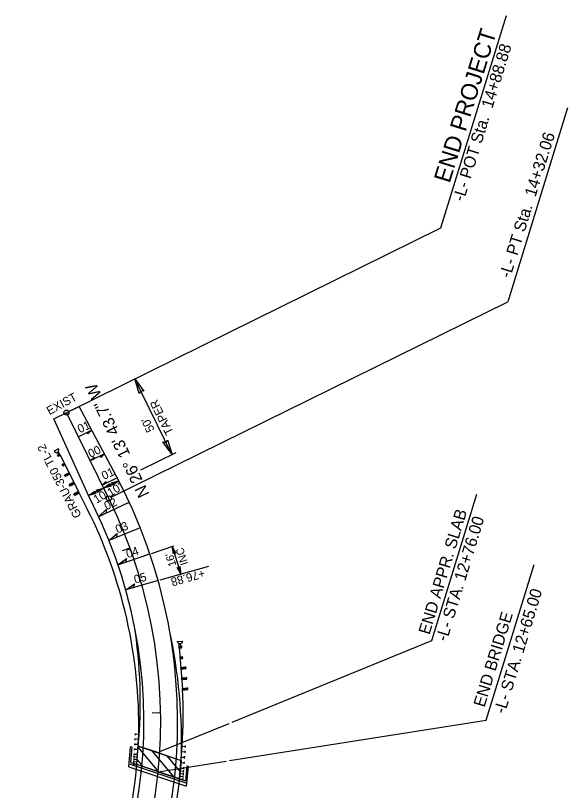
# Model space of a CAD drawing. Extents: x 1348352 to 1349119, y 1028998 to 1029749.
# Drawn here: x 1348790.7 to 1349118.5, y 1029289.4 to 1029749.4 of the extents above; entities that cross this region are included whole.
import ezdxf

# ---------------------------------------------------------------- set-up
doc = ezdxf.new("R2010")
doc.units = 0
for name, color, linetype in [('Default', 7, 'Continuous'), ('Prop Dimension', 7, 'Continuous'), ('Prop Dimension Text', 7, 'Continuous'), ('Prop DSN Text', 7, 'Continuous'), ('Prop EOT', 7, 'Continuous'), ('Prop Guardrail', 7, 'Continuous'), ('Prop Guardrail Anchor Unit CELL', 7, 'Continuous'), ('Prop Horizontal Alignment', 7, 'Continuous'), ('Prop Horizontal Alignment Direction Label', 7, 'Continuous'), ('Prop Horizontal Alignment Station Label', 7, 'Continuous'), ('Prop Horizontal Alignment Tick Small', 7, 'Continuous'), ('Prop Leader Line Medium', 7, 'Continuous'), ('Prop Paved Shoulder', 7, 'Continuous'), ('Prop Roadway Bridge', 7, 'Continuous'), ('Prop Structure Anchor Unit CELL', 7, 'Continuous'), ('Prop Superelevation  Arrow CELL', 7, 'Continuous'), ('Prop Superelevation Label', 7, 'Continuous'), ('Prop Terminator CELL', 7, 'Continuous')]:
    doc.layers.add(name, color=color, linetype=linetype)

msp = doc.modelspace()

# ---------------------------------------------------------------- linework, layer by layer
at = {"layer": 'Default'}
for p, q in [((1348858.09, 1029303.43), (1348858.96, 1029315.21)), ((1348859.96, 1029315.13), (1348858.96, 1029315.21)), ((1348859.27, 1029305.94), (1348859.96, 1029315.13)), ((1348892.5, 1029303.78), (1348891.61, 1029295.07)), ((1348892.3, 1029291.94), (1348893.5, 1029303.68)), ((1348893.5, 1029303.68), (1348892.5, 1029303.78))]:
    msp.add_line(p, q, dxfattribs=at)
for points in [[(1348858.09, 1029303.43), (1348892.3, 1029291.94)], [(1348858.22, 1029305.24), (1348892.48, 1029293.73)], [(1348859.27, 1029305.94), (1348862.2, 1029304.95)], [(1348888.14, 1029296.24), (1348891.61, 1029295.07)]]:
    msp.add_lwpolyline(points, dxfattribs=at)
at = {"layer": 'Prop Dimension'}
for p, q in [((1348883.61, 1029488.84), (1348861.51, 1029533.68)), ((1348836.01, 1029503.29), (1348828.05, 1029499.36)), ((1348843.56, 1029489.17), (1348835.12, 1029485.01)), ((1348865.24, 1029479.79), (1348886.05, 1029490.04)), ((1348834.1, 1029464.45), (1348852.05, 1029473.29)), ((1348851.1, 1029475.05), (1348842.19, 1029470.66)), ((1348840.11, 1029452.07), (1348858.26, 1029460.47)), ((1348864.81, 1029445.29), (1348846.24, 1029437.87)), ((1348871.48, 1029430.11), (1348884.74, 1029434.61)), ((1348883.79, 1029434.29), (1348888.91, 1029417.78)), ((1348851.59, 1029423.36), (1348870.53, 1029429.79)), ((1348905.42, 1029422.42), (1348876.39, 1029414.27)), ((1348875.43, 1029414), (1348856.17, 1029408.59))]:
    msp.add_line(p, q, dxfattribs=at)
at = {"layer": 'Prop EOT'}
for p, q in [((1348813.47, 1029510.02), (1348828.47, 1029517.41)), ((1348852.05, 1029473.29), (1348828.47, 1029517.41)), ((1348834.1, 1029464.45), (1348813.47, 1029510.02)), ((1348855.06, 1029467.16), (1348852.05, 1029473.29)), ((1348837.12, 1029458.33), (1348834.1, 1029464.45))]:
    msp.add_line(p, q, dxfattribs=at)
for radius in [310, 290]:
    msp.add_arc((1348576.98, 1029330.16), radius, 317.4777, 26.2288, dxfattribs=at)
at = {"layer": 'Prop Guardrail'}
msp.add_line((1348828.38, 1029466.35), (1348833.37, 1029456.44), dxfattribs=at)
for centre, radius, start, end in [((1348577.56, 1029327.72), 286.37, 358.983, 26.7112), ((1348591.75, 1029335.59), 298.56, 356.1874, 2.673)]:
    msp.add_arc(centre, radius, start, end, dxfattribs=at)
at = {"layer": 'Prop Guardrail Anchor Unit CELL'}
for p, q in [((1348816.35, 1029492.14), (1348813.73, 1029490.82)), ((1348813.87, 1029490.55), (1348813.73, 1029490.82)), ((1348813.87, 1029490.55), (1348815.16, 1029489.88)), ((1348815.16, 1029489.88), (1348816.25, 1029490.43)), ((1348816.25, 1029490.43), (1348816.49, 1029491.87)), ((1348816.92, 1029489.12), (1348816.25, 1029490.43)), ((1348816.49, 1029491.87), (1348816.35, 1029492.14)), ((1348816.92, 1029489.12), (1348815.57, 1029488.44)), ((1348816.02, 1029487.55), (1348815.57, 1029488.44)), ((1348817.37, 1029488.23), (1348815.57, 1029488.44)), ((1348815.61, 1029490.11), (1348816.27, 1029488.8)), ((1348816.02, 1029487.55), (1348816.92, 1029489.12)), ((1348817.37, 1029488.23), (1348816.02, 1029487.55)), ((1348817.37, 1029488.23), (1348816.92, 1029489.12)), ((1348817.15, 1029488.68), (1348828.38, 1029466.34)), ((1348819.73, 1029483.54), (1348818.38, 1029482.86)), ((1348818.83, 1029481.96), (1348818.38, 1029482.86)), ((1348820.18, 1029482.65), (1348818.38, 1029482.86)), ((1348818.83, 1029481.97), (1348819.73, 1029483.54)), ((1348820.18, 1029482.65), (1348818.83, 1029481.96)), ((1348820.18, 1029482.65), (1348819.73, 1029483.54)), ((1348822.54, 1029477.96), (1348819.83, 1029476.59)), ((1348820.28, 1029475.7), (1348819.83, 1029476.59)), ((1348819.83, 1029476.59), (1348821.63, 1029476.38)), ((1348821.19, 1029477.28), (1348820.28, 1029475.7)), ((1348822.99, 1029477.06), (1348820.28, 1029475.7)), ((1348821.63, 1029476.38), (1348821.19, 1029477.28)), ((1348822.99, 1029477.06), (1348821.19, 1029477.28)), ((1348821.63, 1029476.38), (1348822.54, 1029477.96)), ((1348822.99, 1029477.06), (1348822.54, 1029477.96)), ((1348825.35, 1029472.37), (1348822.64, 1029471.01)), ((1348824.44, 1029470.8), (1348825.35, 1029472.37)), ((1348825.8, 1029471.48), (1348825.35, 1029472.37)), ((1348823.09, 1029470.12), (1348822.64, 1029471.01)), ((1348822.64, 1029471.01), (1348824.44, 1029470.8)), ((1348823.99, 1029471.69), (1348823.09, 1029470.12)), ((1348825.8, 1029471.48), (1348823.09, 1029470.12)), ((1348824.44, 1029470.8), (1348823.99, 1029471.69)), ((1348825.8, 1029471.48), (1348823.99, 1029471.69)), ((1348828.16, 1029466.79), (1348825.45, 1029465.43)), ((1348825.9, 1029464.53), (1348825.45, 1029465.43)), ((1348825.45, 1029465.43), (1348827.25, 1029465.22)), ((1348826.8, 1029466.11), (1348825.9, 1029464.53)), ((1348828.61, 1029465.9), (1348825.9, 1029464.53)), ((1348827.25, 1029465.22), (1348826.8, 1029466.11)), ((1348828.61, 1029465.9), (1348826.8, 1029466.11)), ((1348827.25, 1029465.22), (1348828.16, 1029466.79)), ((1348828.61, 1029465.9), (1348828.16, 1029466.79)), ((1348886.85, 1029377.81), (1348889.78, 1029378.04)), ((1348886.87, 1029377.5), (1348886.85, 1029377.81)), ((1348887.82, 1029376.4), (1348886.87, 1029377.5)), ((1348889.04, 1029376.5), (1348887.82, 1029376.4)), ((1348887.94, 1029374.93), (1348887.82, 1029376.4)), ((1348888.54, 1029376.46), (1348888.66, 1029374.99)), ((1348889.8, 1029377.74), (1348889.04, 1029376.5)), ((1348889.8, 1029377.74), (1348889.78, 1029378.04)), ((1348887.93, 1029374.93), (1348889.44, 1029375.05)), ((1348888.01, 1029373.94), (1348887.93, 1029374.93)), ((1348889.52, 1029374.06), (1348887.93, 1029374.93)), ((1348887.97, 1029374.43), (1348889.98, 1029349.52)), ((1348888.01, 1029373.94), (1348889.44, 1029375.06)), ((1348888.01, 1029373.94), (1348889.52, 1029374.06)), ((1348889.52, 1029374.06), (1348889.44, 1029375.05)), ((1348888.43, 1029368.7), (1348889.95, 1029368.83)), ((1348888.51, 1029367.71), (1348888.43, 1029368.7)), ((1348890.03, 1029367.83), (1348888.43, 1029368.7)), ((1348888.51, 1029367.71), (1348889.95, 1029368.83)), ((1348888.51, 1029367.71), (1348890.03, 1029367.83)), ((1348890.03, 1029367.83), (1348889.95, 1029368.83)), ((1348888.94, 1029362.47), (1348891.96, 1029362.72)), ((1348889.02, 1029361.48), (1348888.94, 1029362.47)), ((1348890.53, 1029361.6), (1348888.94, 1029362.47)), ((1348889.02, 1029361.48), (1348890.45, 1029362.6)), ((1348889.02, 1029361.48), (1348892.04, 1029361.72)), ((1348890.53, 1029361.6), (1348890.45, 1029362.6)), ((1348890.45, 1029362.6), (1348892.04, 1029361.72)), ((1348891.96, 1029362.72), (1348890.53, 1029361.6)), ((1348892.04, 1029361.72), (1348891.96, 1029362.72)), ((1348889.44, 1029356.24), (1348892.46, 1029356.49)), ((1348889.52, 1029355.25), (1348889.44, 1029356.24)), ((1348891.03, 1029355.37), (1348889.44, 1029356.24)), ((1348889.52, 1029355.25), (1348890.95, 1029356.37)), ((1348889.52, 1029355.25), (1348892.55, 1029355.49)), ((1348891.03, 1029355.37), (1348890.95, 1029356.37)), ((1348890.95, 1029356.37), (1348892.55, 1029355.49)), ((1348892.46, 1029356.49), (1348891.03, 1029355.37)), ((1348892.55, 1029355.49), (1348892.46, 1029356.49)), ((1348889.94, 1029350.01), (1348892.97, 1029350.26)), ((1348890.02, 1029349.02), (1348889.94, 1029350.01)), ((1348891.54, 1029349.14), (1348889.94, 1029350.01)), ((1348890.02, 1029349.02), (1348891.46, 1029350.14)), ((1348890.02, 1029349.02), (1348893.05, 1029349.26)), ((1348891.54, 1029349.14), (1348891.46, 1029350.14)), ((1348891.46, 1029350.14), (1348893.05, 1029349.26)), ((1348892.97, 1029350.26), (1348891.54, 1029349.14)), ((1348893.05, 1029349.26), (1348892.97, 1029350.26))]:
    msp.add_line(p, q, dxfattribs=at)
at = {"layer": 'Prop Horizontal Alignment'}
msp.add_line((1348846.09, 1029462.75), (1348820.98, 1029513.72), dxfattribs=at)
msp.add_arc((1348576.98, 1029330.16), 300, 317.4777, 26.2288, dxfattribs=at)
at = {"layer": 'Prop Horizontal Alignment Station Label'}
for p, q in [((1349043.4, 1029623.3), (1349082.23, 1029749.4)), ((1349118.54, 1029694.52), (1349083.13, 1029579.53)), ((1348822.32, 1029514.38), (1349043.4, 1029623.3)), ((1348847.44, 1029463.41), (1349083.13, 1029579.53))]:
    msp.add_line(p, q, dxfattribs=at)
for centre in [(1348820.98, 1029513.72), (1348846.09, 1029462.75)]:
    msp.add_circle(centre, 1.5, dxfattribs=at)
at = {"layer": 'Prop Horizontal Alignment Tick Small'}
for p, q in [((1348858.7, 1029433.29), (1348854, 1029431.57)), ((1348876.93, 1029335.43), (1348871.93, 1029335.35))]:
    msp.add_line(p, q, dxfattribs=at)
at = {"layer": 'Prop Leader Line Medium'}
for p, q in [((1349037.99, 1029378.49), (1349064.7, 1029465.24)), ((1349070.32, 1029331.04), (1349098.78, 1029423.47)), ((1348919.39, 1029330), (1349037.99, 1029378.49)), ((1348876.46, 1029312.44), (1348917.53, 1029329.24)), ((1348917.84, 1029307.12), (1349070.32, 1029331.04)), ((1348875.51, 1029300.48), (1348915.86, 1029306.81))]:
    msp.add_line(p, q, dxfattribs=at)
at = {"layer": 'Prop Paved Shoulder'}
for centre, radius, start, end in [((1348576.55, 1029342.17), 288.28, 354.7393, 9.0875), ((1348578.06, 1029318.19), 311.27, 357.9715, 12.3173)]:
    msp.add_arc(centre, radius, start, end, dxfattribs=at)
at = {"layer": 'Prop Roadway Bridge'}
for p, q in [((1348876.4, 1029311.45), (1348863.62, 1029315.74)), ((1348875.81, 1029300.38), (1348863.57, 1029315.08)), ((1348884.85, 1029297.35), (1348871.83, 1029312.98)), ((1348876.4, 1029311.45), (1348889.13, 1029307.17)), ((1348866.78, 1029303.42), (1348863.07, 1029307.87)), ((1348888.54, 1029300.72), (1348880.86, 1029309.95)), ((1348875.51, 1029300.48), (1348862.85, 1029304.73)), ((1348875.51, 1029300.48), (1348888.14, 1029296.24))]:
    msp.add_line(p, q, dxfattribs=at)
msp.add_lwpolyline([(1348862.85, 1029304.73), (1348863.62, 1029315.74), (1348889.13, 1029307.17), (1348888.14, 1029296.24)], close=True, dxfattribs=at)
for radius, start, end in [(287, 327.9438, 354.9179), (313, 329.0842, 353.7791)]:
    msp.add_arc((1348576.98, 1029330.16), radius, start, end, dxfattribs=at)
at = {"layer": 'Prop Structure Anchor Unit CELL'}
for p, q in [((1348861.77, 1029319.22), (1348861.83, 1029320.31)), ((1348861.94, 1029322.2), (1348862, 1029323.29)), ((1348863.88, 1029322.64), (1348861.97, 1029322.75)), ((1348862.85, 1029304.73), (1348863.88, 1029322.64)), ((1348861.6, 1029316.23), (1348861.66, 1029317.33)), ((1348863.54, 1029316.67), (1348861.63, 1029316.78)), ((1348863.71, 1029319.65), (1348861.8, 1029319.76)), ((1348888.14, 1029296.24), (1348889.65, 1029315.74)), ((1348889.65, 1029315.74), (1348891.73, 1029315.58)), ((1348891.68, 1029314.98), (1348891.77, 1029316.18)), ((1348861.25, 1029310.27), (1348861.32, 1029311.36)), ((1348863.19, 1029310.7), (1348861.28, 1029310.81)), ((1348861.42, 1029313.25), (1348861.49, 1029314.34)), ((1348863.37, 1029313.69), (1348861.46, 1029313.8)), ((1348889.4, 1029312.49), (1348891.48, 1029312.33)), ((1348891.43, 1029311.73), (1348891.52, 1029312.93)), ((1348861, 1029305.79), (1348861.06, 1029306.88)), ((1348862.94, 1029306.23), (1348861.03, 1029306.34)), ((1348861.08, 1029307.28), (1348861.14, 1029308.38)), ((1348863.02, 1029307.72), (1348861.11, 1029307.83)), ((1348861.17, 1029308.77), (1348861.23, 1029309.87)), ((1348863.11, 1029309.21), (1348861.2, 1029309.32)), ((1348889.14, 1029309.24), (1348891.22, 1029309.08)), ((1348890.93, 1029305.23), (1348891.02, 1029306.43)), ((1348891.18, 1029308.48), (1348891.27, 1029309.68)), ((1348860.91, 1029304.3), (1348860.97, 1029305.39)), ((1348862.85, 1029304.73), (1348860.94, 1029304.84)), ((1348888.64, 1029302.74), (1348890.72, 1029302.58)), ((1348888.89, 1029305.99), (1348890.97, 1029305.83)), ((1348890.55, 1029300.36), (1348890.64, 1029301.55)), ((1348890.67, 1029301.98), (1348890.77, 1029303.18)), ((1348888.26, 1029297.87), (1348890.34, 1029297.7)), ((1348888.39, 1029299.49), (1348890.47, 1029299.33)), ((1348888.51, 1029301.12), (1348890.59, 1029300.95)), ((1348890.3, 1029297.11), (1348890.39, 1029298.3)), ((1348890.42, 1029298.73), (1348890.51, 1029299.93)), ((1348888.14, 1029296.24), (1348890.22, 1029296.08)), ((1348890.17, 1029295.48), (1348890.26, 1029296.68))]:
    msp.add_line(p, q, dxfattribs=at)
at = {"layer": 'Prop Superelevation  Arrow CELL'}
for points in [[(1348836.01, 1029503.29), (1348833.76, 1029501.07), (1348833.94, 1029502.27)], [(1348835.12, 1029485.01), (1348837.37, 1029487.24), (1348837.19, 1029486.03)], [(1348843.56, 1029489.17), (1348841.31, 1029486.95), (1348841.48, 1029488.15)], [(1348842.19, 1029470.66), (1348844.44, 1029472.88), (1348844.27, 1029471.68)], [(1348840.11, 1029452.07), (1348844.71, 1029456.4), (1348844.31, 1029454.01)], [(1348846.24, 1029437.87), (1348851.06, 1029441.95), (1348850.53, 1029439.58)], [(1348851.59, 1029423.36), (1348856.63, 1029427.18), (1348855.97, 1029424.85)], [(1348856.17, 1029408.59), (1348861.41, 1029412.14), (1348860.63, 1029409.84)]]:
    msp.add_lwpolyline(points, close=True, dxfattribs=at)
at = {"layer": 'Prop Terminator CELL'}
for points in [[(1348864.17, 1029524.95), (1348861.51, 1029533.68), (1348867.01, 1029526.32), (1348865.06, 1029526.63)], [(1348881.06, 1029497.62), (1348883.66, 1029488.86), (1348878.21, 1029496.26), (1348880.16, 1029495.94)], [(1348847.66, 1029472.03), (1348852.05, 1029473.29), (1348848.32, 1029470.6), (1348848.49, 1029471.57)], [(1348838.69, 1029467.61), (1348843.07, 1029468.87), (1348839.35, 1029466.18), (1348839.52, 1029467.15)], [(1348847.46, 1029470.12), (1348843.07, 1029468.87), (1348846.8, 1029471.55), (1348846.63, 1029470.58)], [(1348838.49, 1029465.7), (1348834.1, 1029464.45), (1348837.83, 1029467.13), (1348837.66, 1029466.16)], [(1348884.46, 1029429.77), (1348883.79, 1029434.29), (1348885.96, 1029430.23), (1348885.02, 1029430.53)], [(1348888.23, 1029422.3), (1348888.91, 1029417.78), (1348886.73, 1029421.83), (1348887.67, 1029421.53)]]:
    msp.add_lwpolyline(points, close=True, dxfattribs=at)

# ---------------------------------------------------------------- texts
at = {"layer": 'Prop Dimension'}
for s, height, rotation, p in [('GRAU-350 TL-2', 5, 117.3746, (1348830.07, 1029452.65)), ('INC', 4.608, 107.2186, (1348893.31, 1029423.92)), ("16'", 4.608, 107.2186, (1348886.32, 1029423.1)), ('+76.88', 5, 195.6907, (1348902.42, 1029420.88))]:
    msp.add_text(s, height=height, rotation=rotation, dxfattribs=at).set_placement(p)
at = {"layer": 'Prop Dimension Text'}
for s, rotation, p in [(' TAPER', 116.7327, (1348885.57, 1029500.32)), (" 50'", 116.7327, (1348874.29, 1029501.87)), ("10'", 31.3243, (1348847.13, 1029463.58)), ("10'", 31.3243, (1348838.91, 1029459.54))]:
    msp.add_text(s, height=5, rotation=rotation, dxfattribs=at).set_placement(p)
at = {"layer": 'Prop DSN Text'}
for s, height, rotation, p in [('END PROJECT', 10, 72.6928, (1349048.53, 1029649.44)), ('END APPR. SLAB', 7, 73.074, (1349036.56, 1029381.49)), ('-L- STA. 12+76.00', 7, 73.074, (1349046.86, 1029377.44)), ('-L- STA. 12+65.00', 7, 73.074, (1349081.31, 1029334.48)), ('END BRIDGE', 7, 73.074, (1349069.21, 1029338.42))]:
    msp.add_text(s, height=height, rotation=rotation, dxfattribs=at).set_placement(p)
at = {"layer": 'Prop Horizontal Alignment Direction Label'}
msp.add_text('N 26%%d 13\' 43.7" W', height=7, rotation=115.8117, dxfattribs=at).set_placement((1348870.44, 1029465.34))
at = {"layer": 'Prop Horizontal Alignment Station Label'}
for s, rotation, p in [('-L- POT Sta.  14+88.88', 72.8873, (1349056.87, 1029638.6)), ('-L- PT Sta.  14+32.06', 72.6928, (1349084.49, 1029593.12))]:
    msp.add_text(s, height=7, rotation=rotation, dxfattribs=at).set_placement(p)
at = {"layer": 'Prop Superelevation Label'}
for s, rotation, p in [('EXIST', 28.7116, (1348810.87, 1029512.11)), ('01', 25.0355, (1348828.97, 1029501.36)), ('00', 25.0355, (1348835.23, 1029486.74)), ('01', 25.0355, (1348843.25, 1029473.66)), ('02', 24.858, (1348844.77, 1029455.72)), ('03', 21.8023, (1348851.29, 1029441.83)), ('04', 18.7465, (1348857.34, 1029427.21)), ('05', 15.6907, (1348861.85, 1029412.05))]:
    msp.add_text(s, height=5, rotation=rotation, dxfattribs=at).set_placement(p)

doc.saveas('drawing.dxf')
